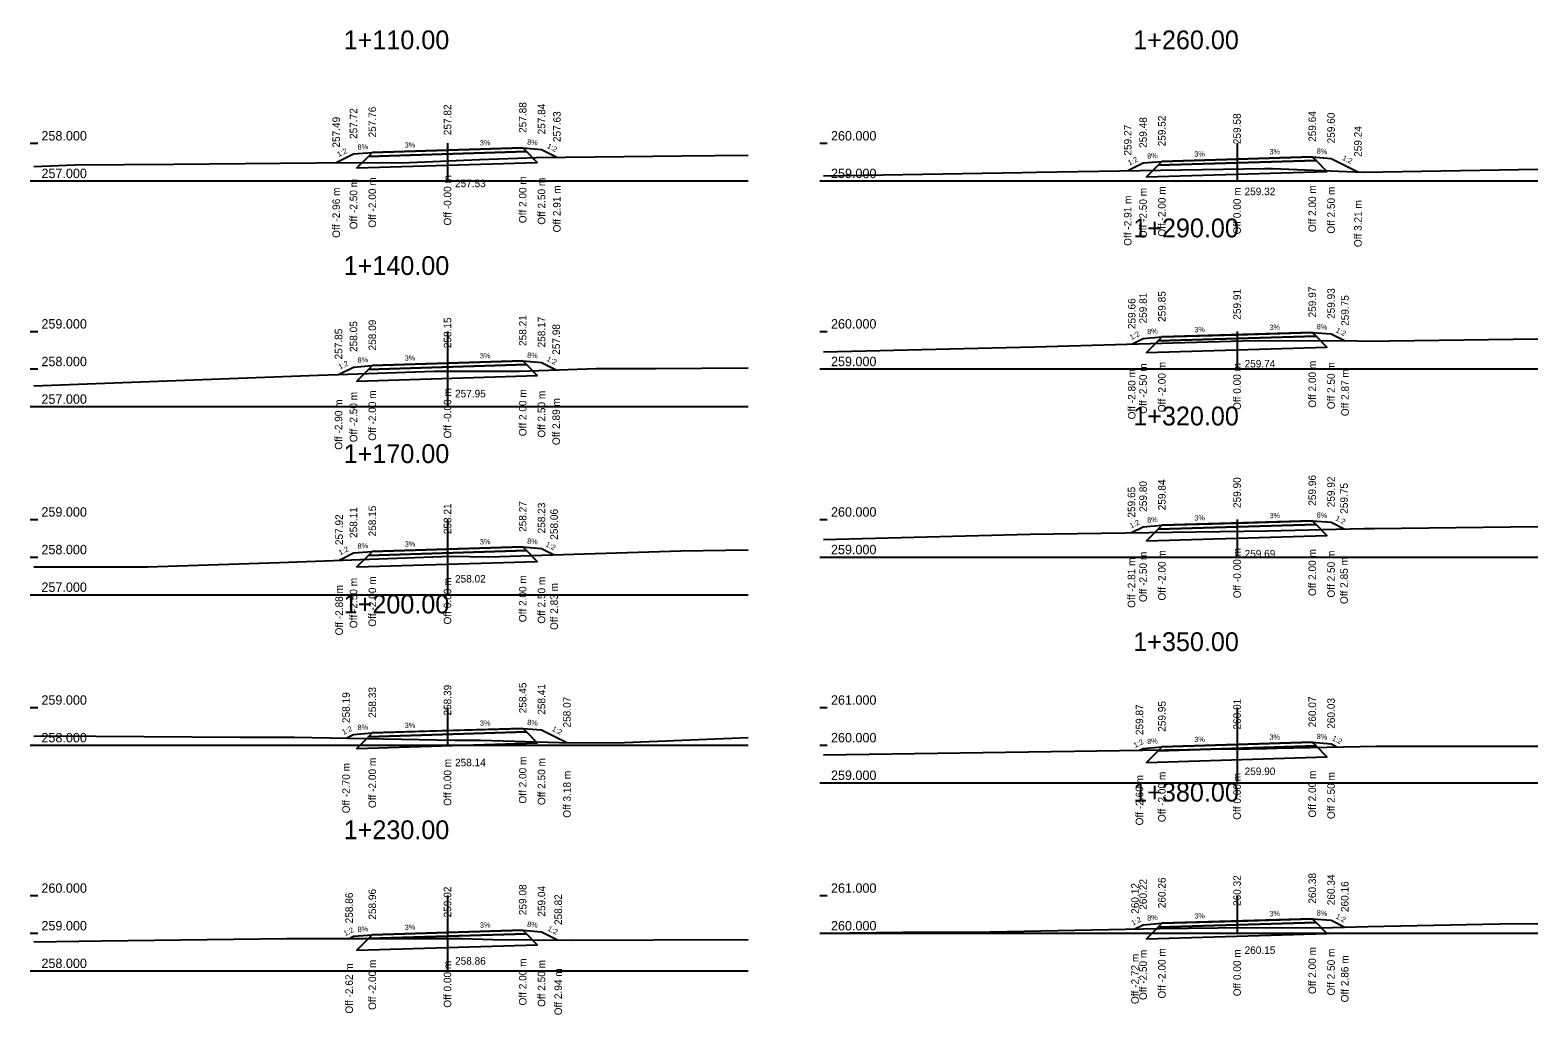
# Model space of a CAD drawing. Extents: x -550605 to -538780, y -1102367 to -1093705.
# Drawn here: x -541205.9 to -541165.8, y -1098198.72 to -1098172.55 of the extents above; entities that cross this region are included whole.
import ezdxf

# ---------------------------------------------------------------- set-up
doc = ezdxf.new("R2010")
doc.units = 0
for name, color, linetype in [('PŘ - offsety od osy', 7, 'Continuous'), ('PŘ - popis', 7, 'Continuous'), ('PŘ - příčné sklony', 7, 'Continuous'), ('PŘ - terén', 7, 'Continuous'), ('PŘ - vozovka', 7, 'Continuous'), ('PŘ - výšky offsetů', 7, 'Continuous')]:
    doc.layers.add(name, color=color, linetype=linetype)

msp = doc.modelspace()

# ---------------------------------------------------------------- linework, layer by layer
at = {"layer": 'PŘ - popis'}
for p, q in [((-541205.898, -1098175.553), (-541205.698, -1098175.553)), ((-541194.798, -1098175.553), (-541194.798, -1098176.553)), ((-541184.898, -1098175.553), (-541184.698, -1098175.553)), ((-541173.798, -1098175.553), (-541173.798, -1098176.553)), ((-541205.898, -1098176.553), (-541205.698, -1098176.553)), ((-541205.798, -1098176.553), (-541186.798, -1098176.553)), ((-541184.898, -1098176.553), (-541184.698, -1098176.553)), ((-541184.798, -1098176.553), (-541165.798, -1098176.553)), ((-541205.898, -1098180.553), (-541205.698, -1098180.553)), ((-541194.798, -1098180.553), (-541194.798, -1098182.553)), ((-541184.898, -1098180.553), (-541184.698, -1098180.553)), ((-541173.798, -1098180.553), (-541173.798, -1098181.553)), ((-541205.898, -1098181.553), (-541205.698, -1098181.553)), ((-541184.898, -1098181.553), (-541184.698, -1098181.553)), ((-541184.798, -1098181.553), (-541165.798, -1098181.553)), ((-541205.898, -1098182.553), (-541205.698, -1098182.553)), ((-541205.798, -1098182.553), (-541186.798, -1098182.553)), ((-541205.898, -1098185.553), (-541205.698, -1098185.553)), ((-541194.798, -1098185.553), (-541194.798, -1098187.553)), ((-541184.898, -1098185.553), (-541184.698, -1098185.553)), ((-541173.798, -1098185.553), (-541173.798, -1098186.553)), ((-541205.898, -1098186.553), (-541205.698, -1098186.553)), ((-541184.898, -1098186.553), (-541184.698, -1098186.553)), ((-541184.798, -1098186.553), (-541165.798, -1098186.553)), ((-541205.898, -1098187.553), (-541205.698, -1098187.553)), ((-541205.798, -1098187.553), (-541186.798, -1098187.553)), ((-541205.898, -1098190.553), (-541205.698, -1098190.553)), ((-541194.798, -1098190.553), (-541194.798, -1098191.553)), ((-541184.898, -1098190.553), (-541184.698, -1098190.553)), ((-541173.798, -1098190.553), (-541173.798, -1098192.553)), ((-541205.898, -1098191.553), (-541205.698, -1098191.553)), ((-541205.798, -1098191.553), (-541186.798, -1098191.553)), ((-541184.898, -1098191.553), (-541184.698, -1098191.553)), ((-541184.898, -1098192.553), (-541184.698, -1098192.553)), ((-541184.798, -1098192.553), (-541165.798, -1098192.553)), ((-541205.898, -1098195.553), (-541205.698, -1098195.553)), ((-541194.798, -1098195.553), (-541194.798, -1098197.553)), ((-541184.898, -1098195.553), (-541184.698, -1098195.553)), ((-541173.798, -1098195.553), (-541173.798, -1098196.553)), ((-541205.898, -1098196.553), (-541205.698, -1098196.553)), ((-541184.898, -1098196.553), (-541184.698, -1098196.553)), ((-541184.798, -1098196.553), (-541165.798, -1098196.553)), ((-541205.898, -1098197.553), (-541205.698, -1098197.553)), ((-541205.798, -1098197.553), (-541186.798, -1098197.553))]:
    msp.add_line(p, q, dxfattribs=at)
at = {"layer": 'PŘ - terén'}
for points in [[(-541205.798, -1098176.166), (-541204.71, -1098176.123), (-541202.08, -1098176.104), (-541198.303, -1098176.068), (-541195.808, -1098176.061), (-541195.807, -1098176.06), (-541193.949, -1098175.984), (-541192.432, -1098175.926), (-541192.432, -1098175.926), (-541192.431, -1098175.926), (-541188.561, -1098175.89), (-541186.798, -1098175.87)], [(-541184.798, -1098176.417), (-541179.517, -1098176.33), (-541179.13, -1098176.319), (-541173.069, -1098176.22), (-541173.066, -1098176.22), (-541172.851, -1098176.221), (-541170.444, -1098176.318), (-541170.443, -1098176.318), (-541170.439, -1098176.318), (-541165.798, -1098176.242)], [(-541184.798, -1098181.099), (-541179.182, -1098180.967), (-541173.341, -1098180.799), (-541173.338, -1098180.799), (-541170.596, -1098180.808), (-541170.394, -1098180.809), (-541165.798, -1098180.749)], [(-541205.798, -1098182.003), (-541198.238, -1098181.717), (-541196.918, -1098181.673), (-541195.145, -1098181.607), (-541195.144, -1098181.607), (-541192.89, -1098181.607), (-541192.107, -1098181.582), (-541192.106, -1098181.582), (-541190.84, -1098181.543), (-541189.267, -1098181.537), (-541186.798, -1098181.523)], [(-541184.798, -1098186.088), (-541179.297, -1098185.941), (-541172.987, -1098185.852), (-541170.423, -1098185.789), (-541170.155, -1098185.79), (-541165.798, -1098185.739)], [(-541205.798, -1098186.809), (-541202.78, -1098186.813), (-541199.27, -1098186.694), (-541194.712, -1098186.525), (-541193.696, -1098186.547), (-541191.724, -1098186.484), (-541188.59, -1098186.389), (-541186.798, -1098186.359)], [(-541205.798, -1098191.312), (-541205.434, -1098191.307), (-541200.302, -1098191.34), (-541198.868, -1098191.339), (-541194.603, -1098191.418), (-541194.603, -1098191.418), (-541193.921, -1098191.424), (-541191.517, -1098191.487), (-541191.514, -1098191.487), (-541190.094, -1098191.48), (-541186.798, -1098191.354)], [(-541184.798, -1098191.812), (-541173.891, -1098191.649), (-541173.47, -1098191.647), (-541173.012, -1098191.643), (-541173.012, -1098191.643), (-541172.741, -1098191.637), (-541170.082, -1098191.581), (-541170.082, -1098191.581), (-541169.312, -1098191.576), (-541168.75, -1098191.578), (-541165.798, -1098191.577)], [(-541184.798, -1098196.548), (-541182.688, -1098196.523), (-541180.367, -1098196.514), (-541175.862, -1098196.424), (-541173.537, -1098196.401), (-541171.569, -1098196.407), (-541170.324, -1098196.376), (-541166.82, -1098196.301), (-541165.798, -1098196.293)], [(-541205.798, -1098196.786), (-541204.004, -1098196.759), (-541199.082, -1098196.691), (-541194.405, -1098196.69), (-541193.591, -1098196.722), (-541191.48, -1098196.738), (-541191.477, -1098196.738), (-541187.158, -1098196.717), (-541186.798, -1098196.729)]]:
    msp.add_lwpolyline(points, dxfattribs=at)
at = {"layer": 'PŘ - vozovka'}
for points in [[(-541197.758, -1098176.067), (-541197.298, -1098175.837), (-541196.798, -1098175.797), (-541194.798, -1098175.737), (-541192.798, -1098175.677), (-541192.298, -1098175.717), (-541191.889, -1098175.921)], [(-541176.706, -1098176.279), (-541176.298, -1098176.075), (-541175.798, -1098176.035), (-541173.798, -1098175.975), (-541171.798, -1098175.915), (-541171.298, -1098175.955), (-541170.583, -1098176.313)], [(-541176.6, -1098180.893), (-541176.298, -1098180.742), (-541175.798, -1098180.702), (-541173.798, -1098180.642), (-541171.798, -1098180.582), (-541171.298, -1098180.622), (-541170.927, -1098180.807)], [(-541197.696, -1098181.699), (-541197.298, -1098181.5), (-541196.798, -1098181.46), (-541194.798, -1098181.4), (-541192.798, -1098181.34), (-541192.298, -1098181.38), (-541191.907, -1098181.576)], [(-541176.607, -1098185.903), (-541176.298, -1098185.749), (-541175.798, -1098185.709), (-541173.798, -1098185.649), (-541171.798, -1098185.589), (-541171.298, -1098185.629), (-541170.952, -1098185.802)], [(-541197.681, -1098186.635), (-541197.298, -1098186.444), (-541196.798, -1098186.404), (-541194.798, -1098186.344), (-541192.798, -1098186.284), (-541192.298, -1098186.324), (-541191.963, -1098186.491)], [(-541197.496, -1098191.365), (-541197.298, -1098191.266), (-541196.798, -1098191.226), (-541194.798, -1098191.166), (-541192.798, -1098191.106), (-541192.298, -1098191.146), (-541191.621, -1098191.484)], [(-541176.394, -1098191.686), (-541176.298, -1098191.638), (-541175.798, -1098191.598), (-541173.798, -1098191.538), (-541171.798, -1098191.478), (-541171.298, -1098191.518), (-541171.127, -1098191.603)], [(-541176.513, -1098196.437), (-541176.298, -1098196.329), (-541175.798, -1098196.289), (-541173.798, -1098196.229), (-541171.798, -1098196.169), (-541171.298, -1098196.209), (-541170.934, -1098196.391)], [(-541197.414, -1098196.691), (-541197.298, -1098196.633), (-541196.798, -1098196.593), (-541194.798, -1098196.533), (-541192.798, -1098196.473), (-541192.298, -1098196.513), (-541191.853, -1098196.735)]]:
    msp.add_lwpolyline(points, dxfattribs=at)
for points in [[(-541196.898, -1098175.9), (-541197.211, -1098176.209), (-541192.409, -1098176.065), (-541192.698, -1098175.774)], [(-541196.798, -1098175.797), (-541196.898, -1098175.9), (-541192.698, -1098175.774), (-541192.798, -1098175.677)], [(-541175.898, -1098176.138), (-541176.211, -1098176.448), (-541171.409, -1098176.304), (-541171.698, -1098176.012)], [(-541175.798, -1098176.035), (-541175.898, -1098176.138), (-541171.698, -1098176.012), (-541171.798, -1098175.915)], [(-541175.798, -1098180.702), (-541175.898, -1098180.805), (-541171.698, -1098180.679), (-541171.798, -1098180.582)], [(-541175.898, -1098180.805), (-541176.211, -1098181.114), (-541171.409, -1098180.97), (-541171.698, -1098180.679)], [(-541196.798, -1098181.46), (-541196.898, -1098181.563), (-541192.698, -1098181.437), (-541192.798, -1098181.34)], [(-541196.898, -1098181.563), (-541197.211, -1098181.873), (-541192.409, -1098181.729), (-541192.698, -1098181.437)], [(-541175.898, -1098185.812), (-541176.211, -1098186.121), (-541171.409, -1098185.977), (-541171.698, -1098185.686)], [(-541175.798, -1098185.709), (-541175.898, -1098185.812), (-541171.698, -1098185.686), (-541171.798, -1098185.589)], [(-541196.898, -1098186.507), (-541197.211, -1098186.816), (-541192.409, -1098186.672), (-541192.698, -1098186.381)], [(-541196.798, -1098186.404), (-541196.898, -1098186.507), (-541192.698, -1098186.381), (-541192.798, -1098186.284)], [(-541196.898, -1098191.329), (-541197.211, -1098191.638), (-541192.409, -1098191.494), (-541192.698, -1098191.203)], [(-541196.798, -1098191.226), (-541196.898, -1098191.329), (-541192.698, -1098191.203), (-541192.798, -1098191.106)], [(-541175.898, -1098191.701), (-541176.211, -1098192.01), (-541171.409, -1098191.866), (-541171.698, -1098191.575)], [(-541175.798, -1098191.598), (-541175.898, -1098191.701), (-541171.698, -1098191.575), (-541171.798, -1098191.478)], [(-541175.798, -1098196.289), (-541175.898, -1098196.392), (-541171.698, -1098196.266), (-541171.798, -1098196.169)], [(-541196.898, -1098196.696), (-541197.211, -1098197.005), (-541192.409, -1098196.861), (-541192.698, -1098196.57)], [(-541196.798, -1098196.593), (-541196.898, -1098196.696), (-541192.698, -1098196.57), (-541192.798, -1098196.473)], [(-541175.898, -1098196.392), (-541176.211, -1098196.702), (-541171.409, -1098196.558), (-541171.698, -1098196.266)]]:
    msp.add_lwpolyline(points, close=True, dxfattribs=at)

# ---------------------------------------------------------------- texts
at = {"layer": 'PŘ - offsety od osy'}
for s, p in [('Off -2.50 m', (-541197.198, -1098177.837)), ('Off -2.00 m', (-541196.698, -1098177.797)), ('Off -0.00 m', (-541194.698, -1098177.737)), ('Off 2.00 m', (-541192.698, -1098177.677)), ('Off 2.50 m', (-541192.198, -1098177.717)), ('Off -2.96 m', (-541197.658, -1098178.067)), ('Off 2.91 m', (-541191.789, -1098177.921)), ('Off -2.91 m', (-541176.606, -1098178.279)), ('Off -2.50 m', (-541176.198, -1098178.075)), ('Off -2.00 m', (-541175.698, -1098178.035)), ('Off 0.00 m', (-541173.698, -1098177.975)), ('Off 2.00 m', (-541171.698, -1098177.915)), ('Off 2.50 m', (-541171.198, -1098177.955)), ('Off 3.21 m', (-541170.483, -1098178.313)), ('Off -2.00 m', (-541175.698, -1098182.702)), ('Off 2.00 m', (-541171.698, -1098182.582)), ('Off 2.50 m', (-541171.198, -1098182.622)), ('Off -2.80 m', (-541176.5, -1098182.893)), ('Off -2.50 m', (-541176.198, -1098182.742)), ('Off 0.00 m', (-541173.698, -1098182.642)), ('Off 2.87 m', (-541170.827, -1098182.807)), ('Off -2.50 m', (-541197.198, -1098183.5)), ('Off -2.00 m', (-541196.698, -1098183.46)), ('Off -0.00 m', (-541194.698, -1098183.4)), ('Off 2.00 m', (-541192.698, -1098183.34)), ('Off 2.50 m', (-541192.198, -1098183.38)), ('Off -2.90 m', (-541197.596, -1098183.699)), ('Off 2.89 m', (-541191.807, -1098183.576)), ('Off -2.81 m', (-541176.507, -1098187.903)), ('Off -2.50 m', (-541176.198, -1098187.749)), ('Off -2.00 m', (-541175.698, -1098187.709)), ('Off -0.00 m', (-541173.698, -1098187.649)), ('Off 2.00 m', (-541171.698, -1098187.589)), ('Off 2.50 m', (-541171.198, -1098187.629)), ('Off 2.85 m', (-541170.852, -1098187.802)), ('Off -2.88 m', (-541197.581, -1098188.635)), ('Off -2.50 m', (-541197.198, -1098188.444)), ('Off -2.00 m', (-541196.698, -1098188.404)), ('Off 0.00 m', (-541194.698, -1098188.344)), ('Off 2.00 m', (-541192.698, -1098188.284)), ('Off 2.50 m', (-541192.198, -1098188.324)), ('Off 2.83 m', (-541191.863, -1098188.491)), ('Off -2.70 m', (-541197.396, -1098193.365)), ('Off -2.00 m', (-541196.698, -1098193.226)), ('Off 0.00 m', (-541194.698, -1098193.166)), ('Off 2.00 m', (-541192.698, -1098193.106)), ('Off 2.50 m', (-541192.198, -1098193.146)), ('Off 3.18 m', (-541191.521, -1098193.484)), ('Off -2.60 m', (-541176.294, -1098193.686)), ('Off -2.00 m', (-541175.698, -1098193.598)), ('Off 0.00 m', (-541173.698, -1098193.538)), ('Off 2.00 m', (-541171.698, -1098193.478)), ('Off 2.50 m', (-541171.198, -1098193.518)), ('Off -2.50 m', (-541176.198, -1098198.329)), ('Off -2.00 m', (-541175.698, -1098198.289)), ('Off 0.00 m', (-541173.698, -1098198.229)), ('Off 2.00 m', (-541171.698, -1098198.169)), ('Off 2.50 m', (-541171.198, -1098198.209)), ('Off -2.62 m', (-541197.314, -1098198.691)), ('Off -2.00 m', (-541196.698, -1098198.593)), ('Off 0.00 m', (-541194.698, -1098198.533)), ('Off 2.00 m', (-541192.698, -1098198.473)), ('Off 2.50 m', (-541192.198, -1098198.513)), ('Off -2.72 m', (-541176.413, -1098198.437)), ('Off 2.86 m', (-541170.834, -1098198.391)), ('Off 2.94 m', (-541191.753, -1098198.735))]:
    msp.add_text(s, height=0.2, rotation=90, dxfattribs=at).set_placement(p)
at = {"layer": 'PŘ - popis'}
for s, height, p in [('1+110.00', 0.5, (-541197.558, -1098173.053)), ('1+260.00', 0.5, (-541176.558, -1098173.053)), ('258.000', 0.25, (-541205.598, -1098175.478)), ('260.000', 0.25, (-541184.598, -1098175.478)), ('257.000', 0.25, (-541205.598, -1098176.478)), ('259.000', 0.25, (-541184.598, -1098176.478)), ('1+290.00', 0.5, (-541176.558, -1098178.053)), ('1+140.00', 0.5, (-541197.558, -1098179.053)), ('259.000', 0.25, (-541205.598, -1098180.478)), ('260.000', 0.25, (-541184.598, -1098180.478)), ('258.000', 0.25, (-541205.598, -1098181.478)), ('259.000', 0.25, (-541184.598, -1098181.478)), ('257.000', 0.25, (-541205.598, -1098182.478)), ('1+320.00', 0.5, (-541176.558, -1098183.053)), ('1+170.00', 0.5, (-541197.558, -1098184.053)), ('259.000', 0.25, (-541205.598, -1098185.478)), ('260.000', 0.25, (-541184.598, -1098185.478)), ('258.000', 0.25, (-541205.598, -1098186.478)), ('259.000', 0.25, (-541184.598, -1098186.478)), ('257.000', 0.25, (-541205.598, -1098187.478)), ('1+200.00', 0.5, (-541197.558, -1098188.053)), ('1+350.00', 0.5, (-541176.558, -1098189.053)), ('259.000', 0.25, (-541205.598, -1098190.478)), ('261.000', 0.25, (-541184.598, -1098190.478)), ('258.000', 0.25, (-541205.598, -1098191.478)), ('260.000', 0.25, (-541184.598, -1098191.478)), ('259.000', 0.25, (-541184.598, -1098192.478)), ('1+380.00', 0.5, (-541176.558, -1098193.053)), ('1+230.00', 0.5, (-541197.558, -1098194.053)), ('260.000', 0.25, (-541205.598, -1098195.478)), ('261.000', 0.25, (-541184.598, -1098195.478)), ('259.000', 0.25, (-541205.598, -1098196.478)), ('260.000', 0.25, (-541184.598, -1098196.478)), ('258.000', 0.25, (-541205.598, -1098197.478))]:
    msp.add_text(s, height=height, dxfattribs=at).set_placement(p)
at = {"layer": 'PŘ - příčné sklony'}
for s, rotation, p in [('1:2', 26.5651, (-541197.69, -1098175.921)), ('8%', 4.5739, (-541197.183, -1098175.728)), ('3%', 1.7184, (-541195.933, -1098175.671)), ('3%', 1.7184, (-541193.933, -1098175.611)), ('8%', 355.4261, (-541192.683, -1098175.586)), ('1:2', 333.4349, (-541192.166, -1098175.671)), ('3%', 1.7184, (-541174.933, -1098175.909)), ('3%', 1.7184, (-541172.933, -1098175.849)), ('8%', 355.4261, (-541171.683, -1098175.825)), ('1:2', 26.5651, (-541176.663, -1098176.146)), ('8%', 4.5739, (-541176.183, -1098175.966)), ('1:2', 333.4349, (-541171.013, -1098175.986)), ('1:2', 26.5651, (-541176.611, -1098180.786)), ('8%', 4.5739, (-541176.183, -1098180.632)), ('3%', 1.7184, (-541174.933, -1098180.576)), ('3%', 1.7184, (-541172.933, -1098180.516)), ('8%', 355.4261, (-541171.683, -1098180.491)), ('1:2', 333.4349, (-541171.185, -1098180.566)), ('1:2', 26.5651, (-541197.658, -1098181.569)), ('8%', 4.5739, (-541197.183, -1098181.391)), ('3%', 1.7184, (-541195.933, -1098181.334)), ('3%', 1.7184, (-541193.933, -1098181.274)), ('8%', 355.4261, (-541192.683, -1098181.25)), ('1:2', 333.4349, (-541192.175, -1098181.33)), ('3%', 1.7184, (-541172.933, -1098185.523)), ('8%', 355.4261, (-541171.683, -1098185.498)), ('1:2', 26.5651, (-541176.614, -1098185.795)), ('8%', 4.5739, (-541176.183, -1098185.64)), ('3%', 1.7184, (-541174.933, -1098185.583)), ('1:2', 333.4349, (-541171.197, -1098185.567)), ('8%', 4.5739, (-541197.183, -1098186.335)), ('3%', 1.7184, (-541195.933, -1098186.278)), ('3%', 1.7184, (-541193.933, -1098186.218)), ('8%', 355.4261, (-541192.683, -1098186.193)), ('1:2', 333.4349, (-541192.203, -1098186.26)), ('1:2', 26.5651, (-541197.651, -1098186.509)), ('8%', 4.5739, (-541197.183, -1098191.156)), ('3%', 1.7184, (-541195.933, -1098191.1)), ('3%', 1.7184, (-541193.933, -1098191.04)), ('8%', 355.4261, (-541192.683, -1098191.015)), ('1:2', 26.5651, (-541197.559, -1098191.284)), ('1:2', 333.4349, (-541192.032, -1098191.167)), ('1:2', 26.5651, (-541176.508, -1098191.631)), ('8%', 4.5739, (-541176.183, -1098191.529)), ('3%', 1.7184, (-541174.933, -1098191.472)), ('3%', 1.7184, (-541172.933, -1098191.412)), ('8%', 355.4261, (-541171.683, -1098191.387)), ('1:2', 333.4349, (-541171.285, -1098191.413)), ('8%', 355.4261, (-541192.683, -1098196.382)), ('1:2', 26.5651, (-541176.567, -1098196.352)), ('8%', 4.5739, (-541176.183, -1098196.22)), ('3%', 1.7184, (-541174.933, -1098196.163)), ('3%', 1.7184, (-541172.933, -1098196.103)), ('8%', 355.4261, (-541171.683, -1098196.078)), ('1:2', 333.4349, (-541171.188, -1098196.152)), ('1:2', 26.5651, (-541197.518, -1098196.631)), ('8%', 4.5739, (-541197.183, -1098196.524)), ('3%', 1.7184, (-541195.933, -1098196.467)), ('3%', 1.7184, (-541193.933, -1098196.407)), ('1:2', 333.4349, (-541192.148, -1098196.476))]:
    msp.add_text(s, height=0.14, rotation=rotation, dxfattribs=at).set_placement(p)
at = {"layer": 'PŘ - výšky offsetů'}
for s, p in [('257.82', (-541194.698, -1098175.337)), ('257.88', (-541192.698, -1098175.277)), ('257.84', (-541192.198, -1098175.317)), ('257.49', (-541197.658, -1098175.667)), ('257.72', (-541197.198, -1098175.437)), ('257.76', (-541196.698, -1098175.397)), ('257.63', (-541191.789, -1098175.521)), ('259.48', (-541176.198, -1098175.675)), ('259.52', (-541175.698, -1098175.635)), ('259.58', (-541173.698, -1098175.575)), ('259.64', (-541171.698, -1098175.515)), ('259.60', (-541171.198, -1098175.555)), ('259.27', (-541176.606, -1098175.879)), ('259.24', (-541170.483, -1098175.913)), ('259.97', (-541171.698, -1098180.182)), ('259.66', (-541176.5, -1098180.493)), ('259.81', (-541176.198, -1098180.342)), ('259.85', (-541175.698, -1098180.302)), ('259.91', (-541173.698, -1098180.242)), ('259.93', (-541171.198, -1098180.222)), ('259.75', (-541170.827, -1098180.407)), ('258.15', (-541194.698, -1098181)), ('258.21', (-541192.698, -1098180.94)), ('258.17', (-541192.198, -1098180.98)), ('257.85', (-541197.596, -1098181.299)), ('258.05', (-541197.198, -1098181.1)), ('258.09', (-541196.698, -1098181.06)), ('257.98', (-541191.807, -1098181.176)), ('259.80', (-541176.198, -1098185.349)), ('259.84', (-541175.698, -1098185.309)), ('259.90', (-541173.698, -1098185.249)), ('259.96', (-541171.698, -1098185.189)), ('259.92', (-541171.198, -1098185.229)), ('259.75', (-541170.852, -1098185.402)), ('259.65', (-541176.507, -1098185.503)), ('258.11', (-541197.198, -1098186.044)), ('258.15', (-541196.698, -1098186.004)), ('258.21', (-541194.698, -1098185.944)), ('258.27', (-541192.698, -1098185.884)), ('258.23', (-541192.198, -1098185.924)), ('258.06', (-541191.863, -1098186.091)), ('257.92', (-541197.581, -1098186.235)), ('258.19', (-541197.396, -1098190.965)), ('258.33', (-541196.698, -1098190.826)), ('258.39', (-541194.698, -1098190.766)), ('258.45', (-541192.698, -1098190.706)), ('258.41', (-541192.198, -1098190.746)), ('258.07', (-541191.521, -1098191.084)), ('259.87', (-541176.294, -1098191.286)), ('259.95', (-541175.698, -1098191.198)), ('260.01', (-541173.698, -1098191.138)), ('260.07', (-541171.698, -1098191.078)), ('260.03', (-541171.198, -1098191.118)), ('260.32', (-541173.698, -1098195.829)), ('260.38', (-541171.698, -1098195.769)), ('260.34', (-541171.198, -1098195.809)), ('258.96', (-541196.698, -1098196.193)), ('259.02', (-541194.698, -1098196.133)), ('259.08', (-541192.698, -1098196.073)), ('259.04', (-541192.198, -1098196.113)), ('260.12', (-541176.413, -1098196.037)), ('260.22', (-541176.198, -1098195.929)), ('260.26', (-541175.698, -1098195.889)), ('260.16', (-541170.834, -1098195.991)), ('258.86', (-541197.314, -1098196.291)), ('258.82', (-541191.753, -1098196.335))]:
    msp.add_text(s, height=0.2, rotation=90, dxfattribs=at).set_placement(p)
for s, p in [('257.53', (-541194.598, -1098176.719)), ('259.32', (-541173.598, -1098176.932)), ('259.74', (-541173.598, -1098181.512)), ('257.95', (-541194.598, -1098182.307)), ('259.69', (-541173.598, -1098186.563)), ('258.02', (-541194.598, -1098187.229)), ('258.14', (-541194.598, -1098192.115)), ('259.90', (-541173.598, -1098192.348)), ('260.15', (-541173.598, -1098197.104)), ('258.86', (-541194.598, -1098197.39))]:
    msp.add_text(s, height=0.2, dxfattribs=at).set_placement(p)

doc.saveas('drawing.dxf')
